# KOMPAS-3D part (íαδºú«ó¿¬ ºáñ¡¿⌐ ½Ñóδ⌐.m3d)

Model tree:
1. Эскиз:2
2. Операция выдавливания:1
     Расстояние 1 = 43; Расстояние 2 = 1.7
3. Эскиз:3
4. Вырезать элемент выдавливания:1
     Расстояние 1 = 41
5. Скругление:1
     Радиус = 3
6. Скругление:3
     Радиус = 3

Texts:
  брызговик задний левый
  Полипропилен  ГОСТ 26996-86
